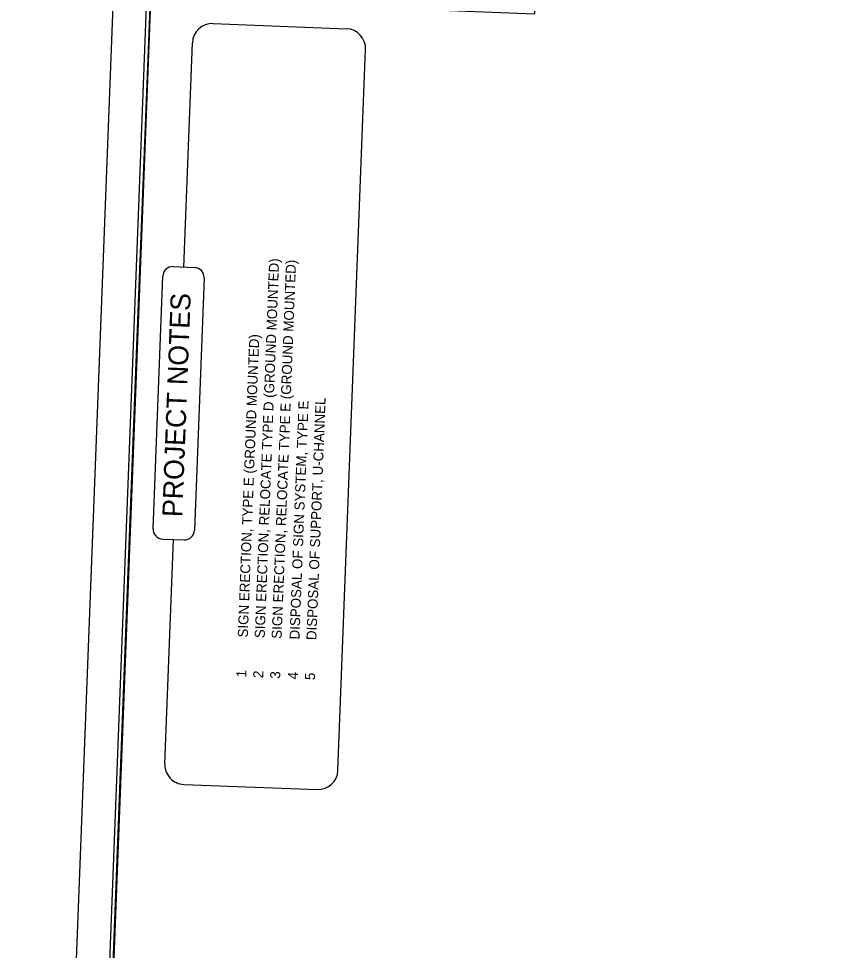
# Model space of a CAD drawing. Extents: x 2093420 to 2100301, y 676254 to 688367.
# Drawn here: x 2097099 to 2097581, y 687418 to 687978 of the extents above; entities that cross this region are included whole.
import ezdxf

# ---------------------------------------------------------------- set-up
doc = ezdxf.new("R2010")
doc.units = 0
for name, color, linetype in [('Default', 7, 'Continuous'), ('Scratch_Level_2', 7, 'Continuous'), ('Sheet Layout Plan Border', 7, 'Continuous'), ('Sheet Plan CELL', 7, 'Continuous'), ('Sheet Plot Border Inside CELL', 7, 'Continuous'), ('Sheet Plot Border Outside CELL', 7, 'Continuous'), ('Sheet Title CELL', 7, 'Continuous')]:
    doc.layers.add(name, color=color, linetype=linetype)

msp = doc.modelspace()

# ---------------------------------------------------------------- linework, layer by layer
at = {"layer": 'Scratch_Level_2'}
msp.add_lwpolyline([(2098179.19, 686705.44), (2097129.59, 686735.95), (2097169.5, 687776.57), (2097177.9, 687989.79), (2097203.71, 687988.8), (2097408.56, 687980.94), (2097412.42, 688081.55), (2098157.98, 688052.95), (2098148.3, 687800.71), (2098221.09, 687797.91)], close=True, dxfattribs=at)
at = {"layer": 'Sheet Layout Plan Border'}
msp.add_lwpolyline([(2098179.19, 686705.44), (2097129.59, 686735.95), (2097169.5, 687776.57), (2097177.9, 687989.79), (2097203.71, 687988.8), (2097408.56, 687980.94), (2097412.42, 688081.55), (2098157.98, 688052.95), (2098148.3, 687800.71), (2098221.09, 687797.91)], close=True, dxfattribs=at)
at = {"layer": 'Sheet Plan CELL'}
msp.add_lwpolyline([(2097185.06, 688176.42), (2097127.55, 686677.48), (2098176.77, 686637.22), (2098234.29, 688136.13)], close=True, dxfattribs=at)
msp.add_lwpolyline([(2097185.06, 688176.42), (2097127.55, 686677.48), (2098176.77, 686637.22), (2098234.29, 688136.13)], close=True, dxfattribs=at)
at = {"layer": 'Sheet Plot Border Inside CELL'}
msp.add_lwpolyline([(2098173.4, 686483.75), (2098237.27, 688148.52), (2097183.06, 688188.98), (2097119.17, 686524.21)], close=True, dxfattribs=at)
msp.add_lwpolyline([(2098173.4, 686483.75), (2098237.27, 688148.52), (2097183.06, 688188.98), (2097119.17, 686524.21)], close=True, dxfattribs=at)
at = {"layer": 'Sheet Plot Border Outside CELL'}
msp.add_lwpolyline([(2098192.89, 686470), (2098257.44, 688152.26), (2097163.24, 688194.24), (2097098.69, 686511.98)], close=True, dxfattribs=at)
msp.add_lwpolyline([(2098192.89, 686470), (2098257.44, 688152.26), (2097163.24, 688194.24), (2097098.69, 686511.98)], close=True, dxfattribs=at)
at = {"layer": 'Sheet Title CELL'}
for p, q in [((2097215.44, 687975.01), (2097295.4, 687971.95)), ((2097197.83, 687828.79), (2097202.99, 687963.48)), ((2097290.33, 687526.53), (2097306.93, 687959.49)), ((2097191.4, 687829.04), (2097204.25, 687828.54)), ((2097179.36, 687671.67), (2097185.18, 687823.27)), ((2097210.01, 687822.32), (2097204.2, 687670.72)), ((2097185.13, 687665.45), (2097197.97, 687664.96)), ((2097186.39, 687530.51), (2097191.55, 687665.2)), ((2097197.92, 687518.06), (2097277.88, 687514.99))]:
    msp.add_line(p, q, dxfattribs=at)
for centre, radius, start, end in [((2097214.98, 687963.02), 12, 87.8037, 177.8037), ((2097294.94, 687959.95), 12, 357.8037, 87.8037), ((2097191.17, 687823.04), 6, 87.8037, 177.8037), ((2097204.02, 687822.55), 6, 357.8037, 87.8037), ((2097185.36, 687671.45), 6, 177.8037, 267.8037), ((2097198.2, 687670.95), 6, 267.8037, 357.8037), ((2097198.38, 687530.05), 12, 177.8037, 267.8037), ((2097278.34, 687526.99), 12, 267.8037, 357.8037)]:
    msp.add_arc(centre, radius, start, end, dxfattribs=at)

# ---------------------------------------------------------------- texts
at = {"layer": 'Default'}
for s, height, p in [('SIGN ERECTION, RELOCATE TYPE D (GROUND MOUNTED)', 6, (2097246.35, 687605.83)), ('SIGN ERECTION, RELOCATE TYPE E (GROUND MOUNTED)', 6, (2097256.51, 687605.44)), ('PROJECT NOTES', 12, (2097196.88, 687678.45)), ('SIGN ERECTION, TYPE E (GROUND MOUNTED)', 6, (2097236.19, 687606.21)), ('DISPOSAL OF SIGN SYSTEM, TYPE E', 6, (2097267.22, 687605.02)), ('DISPOSAL OF SUPPORT, U-CHANNEL', 6, (2097277.38, 687604.64)), ('1', 6, (2097235.27, 687582.23)), ('2', 6, (2097245.43, 687581.84)), ('3', 6, (2097255.59, 687581.45)), ('4', 6, (2097266.3, 687581.04)), ('5', 6, (2097276.46, 687580.65))]:
    msp.add_text(s, height=height, rotation=87.8037, dxfattribs=at).set_placement(p)

doc.saveas('drawing.dxf')
